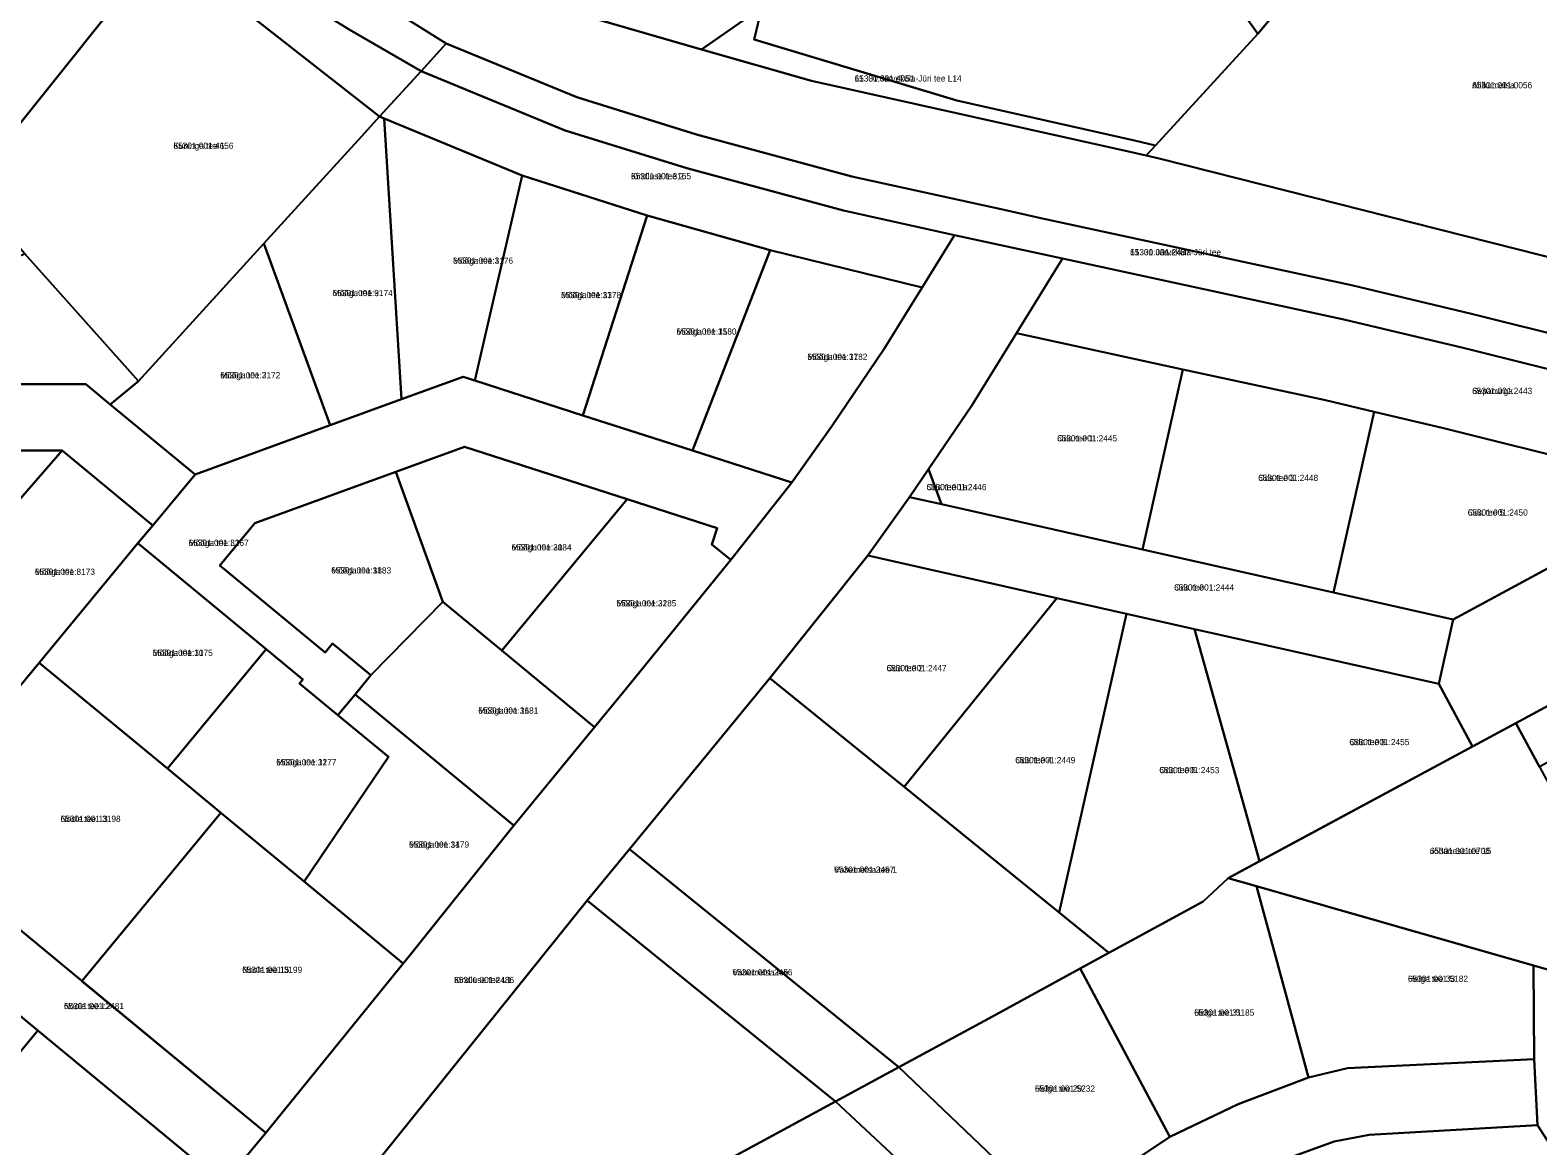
# Model space of a CAD drawing. Extents: x 543236 to 563717, y 6566033 to 6588992.
# Drawn here: x 546570 to 546934.3, y 6582798.1 to 6583067.8 of the extents above; entities that cross this region are included whole.
import ezdxf

# ---------------------------------------------------------------- set-up
doc = ezdxf.new("R2010")
doc.units = 0
for name, color, linetype in [('L_AADRESS', 7, 'Continuous'), ('PIIR', 7, 'Continuous'), ('TUNNUS', 7, 'Continuous')]:
    doc.layers.add(name, color=color, linetype=linetype)

msp = doc.modelspace()

# ---------------------------------------------------------------- linework, layer by layer
at = {"layer": 'PIIR'}
for points in [[(546824.7, 6583127.22), (546857.69, 6583150.07), (546891.19, 6583101.69), (546893.24, 6583098.72), (546866.63, 6583066.87), (546863.9, 6583070.8)], [(546744.91, 6583065.56), (546746.77, 6583073.24), (546824.7, 6583127.22), (546863.9, 6583070.8), (546866.63, 6583066.87), (546841.91, 6583039.95), (546836.85, 6583041.1), (546793.9, 6583050.82)], [(546601.81, 6583088.17), (546579.76, 6583110.6), (546587.72, 6583117.51), (546608.42, 6583096.43), (546617.02, 6583089.31), (546631.52, 6583077.62), (546647.09, 6583067.98), (546664.44, 6583057.9), (546654.4, 6583046.93)], [(546592.18, 6583076.12), (546569.09, 6583101.29), (546579.76, 6583110.6), (546601.81, 6583088.17), (546654.4, 6583046.93), (546650.13, 6583042.2), (546634.72, 6583025.32), (546626.48, 6583016.25), (546596.15, 6582982.97), (546568.74, 6583013.76), (546554.83, 6583029.43)], [(546613.46, 6583102.71), (546629.64, 6583090.21), (546650.79, 6583076.96), (546670.53, 6583064.59), (546664.44, 6583057.9), (546647.09, 6583067.98), (546631.52, 6583077.62), (546617.02, 6583089.31), (546608.42, 6583096.43)], [(546534.12, 6583087.49), (546566.53, 6583099.04), (546569.09, 6583101.29), (546592.18, 6583076.12), (546554.83, 6583029.43), (546551.45, 6583038.88)], [(546839.65, 6583037.5), (546841.91, 6583039.95), (546866.63, 6583066.87), (546893.24, 6583098.72), (546896.91, 6583097.6), (546991.71, 6583068.46), (546953.5, 6583008.77), (546843.14, 6583036.66)], [(546758.82, 6583055.55), (546732.2, 6583063.15), (546746.77, 6583073.24), (546744.91, 6583065.56), (546793.9, 6583050.82), (546836.85, 6583041.1), (546841.91, 6583039.95), (546839.65, 6583037.5), (546835.39, 6583038.45)], [(546456.84, 6583059.94), (546471.94, 6583065.32), (546476.92, 6583067.09), (546478.83, 6583061.73), (546473.85, 6583059.96), (546478.92, 6583045.71), (546502.02, 6583033.43), (546505.87, 6583022.63), (546515.78, 6582994.85), (546520.29, 6582982.2), (546583.47, 6582982.2), (546589.34, 6582977.35), (546609.88, 6582960.38), (546599.62, 6582948.1), (546577.72, 6582966.2), (546509.01, 6582966.2), (546489.73, 6583020.25), (546489.03, 6583022.22), (546465.95, 6583034.48)], [(546670.53, 6583064.59), (546702.13, 6583051.56), (546731.04, 6583042.61), (546768.56, 6583032.44), (546805.33, 6583024.33), (546814.25, 6583022.37), (546889.3, 6583006.12), (546918.28, 6582999.27), (546993.56, 6582980.46), (547036.14, 6582972.21), (547055.46, 6582968.62), (547045.02, 6582962.99), (547043.55, 6582962.16), (546991.71, 6582972.17), (546916.25, 6582991.02), (546887.44, 6582997.84), (546819.45, 6583012.57), (546793.36, 6583018.28), (546766.52, 6583024.18), (546728.68, 6583034.46), (546699.25, 6583043.54), (546664.44, 6583057.9)], [(546664.44, 6583057.9), (546699.25, 6583043.54), (546728.68, 6583034.46), (546766.52, 6583024.18), (546793.36, 6583018.28), (546785.54, 6583005.61), (546748.79, 6583014.62), (546719.11, 6583022.96), (546688.86, 6583032.68), (546655.52, 6583046.44), (546654.4, 6583046.93)], [(546654.4, 6583046.93), (546655.52, 6583046.44), (546659.72, 6582978.58), (546642.53, 6582972.3), (546626.49, 6583016.26), (546634.72, 6583025.32), (546650.13, 6583042.2)], [(546655.52, 6583046.44), (546688.86, 6583032.68), (546677.47, 6582983.09), (546674.61, 6582984.01), (546659.72, 6582978.58)], [(546688.86, 6583032.68), (546719.11, 6583022.96), (546703.57, 6582974.69), (546677.47, 6582983.09)], [(546719.11, 6583022.96), (546748.79, 6583014.62), (546730.06, 6582966.17), (546703.57, 6582974.69)], [(546626.49, 6583016.26), (546642.53, 6582972.3), (546609.88, 6582960.38), (546589.34, 6582977.35), (546596.16, 6582982.98)], [(546748.79, 6583014.62), (546785.54, 6583005.61), (546782.23, 6583000.25), (546776.38, 6582990.78), (546763.71, 6582972.09), (546754.02, 6582958.46), (546730.06, 6582966.17)], [(546515.78, 6582994.85), (546568.74, 6583013.76), (546596.15, 6582982.97), (546589.34, 6582977.35), (546583.47, 6582982.2), (546520.29, 6582982.2)], [(546819.45, 6583012.57), (546887.44, 6582997.84), (546916.25, 6582991.02), (546991.71, 6582972.17), (547043.55, 6582962.16), (547015.74, 6582947.15), (546987.39, 6582952.63), (546948.33, 6582962.39), (546911.52, 6582971.59), (546894.72, 6582975.56), (546883.02, 6582978.33), (546848.55, 6582985.79), (546808.3, 6582994.52)], [(546808.3, 6582994.52), (546848.55, 6582985.79), (546838.75, 6582942.28), (546790.19, 6582953.21), (546787.09, 6582961.67), (546797.54, 6582977.08)], [(546848.55, 6582985.79), (546883.02, 6582978.33), (546894.72, 6582975.56), (546884.9, 6582931.9), (546838.75, 6582942.28)], [(546609.88, 6582960.38), (546642.53, 6582972.3), (546659.72, 6582978.58), (546674.61, 6582984.01), (546677.47, 6582983.09), (546703.57, 6582974.69), (546730.06, 6582966.17), (546754.02, 6582958.46), (546739.34, 6582939.78), (546734.7, 6582943.49), (546735.98, 6582947.46), (546714.24, 6582954.45), (546674.94, 6582967.1), (546658.39, 6582961.06), (546624.28, 6582948.6), (546615.87, 6582938.43), (546641.31, 6582917.41), (546643.07, 6582919.54), (546652.32, 6582911.9), (546648.5, 6582907.27), (546644.36, 6582902.26), (546635.11, 6582909.9), (546635.9, 6582910.86), (546627.02, 6582918.19), (546596.05, 6582943.78), (546599.62, 6582948.1)], [(546894.72, 6582975.56), (546911.52, 6582971.59), (546948.33, 6582962.39), (546943.61, 6582941.43), (546913.87, 6582925.38), (546884.9, 6582931.9)], [(546509.01, 6582966.2), (546577.72, 6582966.2), (546542.69, 6582925.9), (546538.28, 6582929.54), (546515.31, 6582948.52)], [(546577.72, 6582966.2), (546599.62, 6582948.1), (546596.05, 6582943.78), (546572.2, 6582914.91), (546565.62, 6582906.95), (546542.69, 6582925.9)], [(546658.39, 6582961.06), (546674.94, 6582967.1), (546714.24, 6582954.45), (546683.98, 6582917.84), (546669.7, 6582929.64)], [(546624.28, 6582948.6), (546658.39, 6582961.06), (546669.7, 6582929.64), (546652.32, 6582911.9), (546643.07, 6582919.54), (546641.31, 6582917.41), (546615.87, 6582938.43)], [(546787.09, 6582961.67), (546790.19, 6582953.21), (546782.44, 6582954.95)], [(546948.33, 6582962.39), (546987.39, 6582952.63), (547015.74, 6582947.15), (546928.97, 6582900.33), (546918.5, 6582894.68), (546910.35, 6582909.77), (546913.87, 6582925.38), (546943.61, 6582941.43)], [(547043.55, 6582962.16), (547045.02, 6582962.99), (547053.27, 6582961.5), (547068.09, 6582961.29), (547058.83, 6582956.3), (547047.81, 6582950.34), (547035.02, 6582943.44), (546994.72, 6582921.68), (547023.22, 6582868.88), (547012.66, 6582863.18), (547003.63, 6582879.9), (547007.15, 6582881.8), (546987.94, 6582917.39), (546981.16, 6582919.42), (546943.32, 6582898.99), (546945.22, 6582895.47), (546934.67, 6582889.77), (546928.97, 6582900.33), (547015.74, 6582947.15)], [(546714.24, 6582954.45), (546735.98, 6582947.46), (546734.7, 6582943.49), (546739.34, 6582939.78), (546713.46, 6582907.92), (546706.4, 6582899.32), (546683.98, 6582917.84)], [(546782.44, 6582954.95), (546790.19, 6582953.21), (546838.75, 6582942.28), (546884.9, 6582931.9), (546913.87, 6582925.38), (546910.35, 6582909.77), (546851.31, 6582923.05), (546834.91, 6582926.75), (546818.1, 6582930.53), (546772.39, 6582940.81)], [(546596.05, 6582943.78), (546627.02, 6582918.19), (546603.15, 6582889.34), (546572.2, 6582914.91)], [(546772.39, 6582940.81), (546818.1, 6582930.53), (546781.16, 6582884.91), (546748.72, 6582911.17)], [(546669.7, 6582929.64), (546683.98, 6582917.84), (546706.4, 6582899.32), (546686.88, 6582875.56), (546648.5, 6582907.27), (546652.32, 6582911.9)], [(546818.1, 6582930.53), (546834.91, 6582926.75), (546818.62, 6582854.57), (546781.16, 6582884.91)], [(546834.91, 6582926.75), (546851.31, 6582923.05), (546867.06, 6582866.92), (546859.5, 6582862.82), (546853.4, 6582857.23), (546830.61, 6582844.81), (546818.62, 6582854.57)], [(546851.31, 6582923.05), (546910.35, 6582909.77), (546918.5, 6582894.68), (546867.06, 6582866.92)], [(546627.02, 6582918.19), (546635.9, 6582910.86), (546635.11, 6582909.9), (546644.36, 6582902.26), (546656.57, 6582892.17), (546636.23, 6582862.02), (546616.11, 6582878.64), (546603.15, 6582889.34)], [(546572.2, 6582914.91), (546603.15, 6582889.34), (546616.11, 6582878.64), (546582.51, 6582837.98), (546582.05, 6582838.36), (546539.65, 6582873.39), (546538.61, 6582874.25), (546565.62, 6582906.95)], [(546748.72, 6582911.17), (546781.16, 6582884.91), (546818.62, 6582854.57), (546830.61, 6582844.81), (546823.73, 6582840.99), (546802.52, 6582829.41), (546779.87, 6582817.15), (546714.78, 6582869.82)], [(546648.5, 6582907.27), (546686.88, 6582875.56), (546686.47, 6582875.06), (546661.61, 6582844.02), (546660.17, 6582842.24), (546636.23, 6582862.02), (546656.57, 6582892.17), (546644.36, 6582902.26)], [(546928.97, 6582900.33), (546934.67, 6582889.77), (546954.35, 6582853.3), (546949.62, 6582837.04), (546933.24, 6582841.73), (546866.3, 6582860.88), (546859.5, 6582862.82)], [(546616.11, 6582878.64), (546636.23, 6582862.02), (546660.17, 6582842.24), (546626.94, 6582801.27), (546582.51, 6582837.98)], [(546529.46, 6582861.05), (546539.65, 6582873.39), (546582.05, 6582838.36), (546626.94, 6582801.27), (546616.68, 6582788.99), (546571.86, 6582826.02)], [(546714.78, 6582869.82), (546779.87, 6582817.15), (546764.57, 6582808.86), (546704.61, 6582857.46)], [(546845.35, 6582800.32), (546823.73, 6582840.99), (546830.61, 6582844.81), (546853.4, 6582857.23), (546859.5, 6582862.82), (546866.3, 6582860.88), (546878.85, 6582814.7), (546861.89, 6582808.2)], [(546493.83, 6582817.93), (546529.46, 6582861.05), (546571.86, 6582826.02), (546536.23, 6582782.9), (546510.39, 6582804.25)], [(546878.85, 6582814.7), (546866.3, 6582860.88), (546933.24, 6582841.73), (546933.45, 6582819.12), (546888.35, 6582816.91)], [(546704.61, 6582857.46), (546764.57, 6582808.86), (546722.52, 6582786.05), (546678.14, 6582762.03), (546665.85, 6582755.32), (546633.59, 6582737.86), (546585.24, 6582711.61), (546584.34, 6582711.11), (546651.49, 6582791.37)], [(546817.24, 6582781.51), (546779.87, 6582817.15), (546802.52, 6582829.41), (546823.73, 6582840.99), (546845.35, 6582800.32)], [(546933.45, 6582819.12), (546933.24, 6582841.73), (546949.62, 6582837.04), (546968.88, 6582831.7), (546990.21, 6582825.54), (546994.88, 6582809.22), (546948.14, 6582784.9), (546946.5, 6582784.11), (546934.26, 6582803.13)], [(546536.23, 6582782.9), (546571.86, 6582826.02), (546616.68, 6582788.99), (546580.62, 6582746.23), (546539.15, 6582780.49)], [(546793.59, 6582781.78), (546764.57, 6582808.86), (546779.87, 6582817.15), (546817.24, 6582781.51), (546798.93, 6582771.65)], [(546756.97, 6582749.43), (546722.52, 6582786.05), (546764.57, 6582808.86), (546793.59, 6582781.78), (546798.93, 6582771.65)], [(546891.86, 6582757.53), (546873.6, 6582795.04), (546885.11, 6582799.19), (546893.51, 6582800.81), (546934.26, 6582803.13), (546946.5, 6582784.11), (546900.82, 6582761.74)]]:
    msp.add_lwpolyline(points, close=True, dxfattribs=at)
for points in [[(547294.1, 6582901.21), (547206.95, 6582950.98), (547196.64, 6582953.98), (547152.11, 6582958.67), (547122.02, 6582961.9), (547060.4, 6582971.13), (547055.46, 6582968.62), (547036.14, 6582972.21), (546993.56, 6582980.46), (546918.28, 6582999.27), (546889.3, 6583006.12), (546814.25, 6583022.37), (546805.33, 6583024.33), (546768.56, 6583032.44), (546731.04, 6583042.61), (546702.13, 6583051.56), (546670.53, 6583064.59), (546650.79, 6583076.96)], [(546746.77, 6583073.24), (546732.2, 6583063.15), (546707.4, 6583070.31)], [(546707.4, 6583070.31), (546732.2, 6583063.15), (546758.82, 6583055.55), (546835.39, 6583038.45), (546839.65, 6583037.5), (546843.14, 6583036.66), (546953.5, 6583008.77), (547033.94, 6582990.72), (547039.08, 6582989.6), (547095.89, 6582981.55), (547195.38, 6582971.01), (547213.24, 6582965.81), (547223.73, 6582959.82)], [(546616.68, 6582788.99), (546626.94, 6582801.27), (546660.17, 6582842.24), (546661.61, 6582844.02), (546686.47, 6582875.06), (546706.4, 6582899.32), (546713.46, 6582907.92), (546739.34, 6582939.78), (546754.02, 6582958.46), (546763.71, 6582972.09), (546776.38, 6582990.78), (546782.23, 6583000.25), (546785.54, 6583005.61), (546793.36, 6583018.28), (546819.45, 6583012.57), (546808.3, 6582994.52), (546797.54, 6582977.08), (546787.09, 6582961.67), (546782.44, 6582954.95), (546772.39, 6582940.81), (546748.72, 6582911.17), (546714.78, 6582869.82), (546704.61, 6582857.46), (546651.49, 6582791.37)], [(546817.24, 6582781.51), (546845.35, 6582800.32), (546861.89, 6582808.2), (546878.85, 6582814.7), (546888.35, 6582816.91), (546933.45, 6582819.12), (546934.26, 6582803.13), (546893.51, 6582800.81), (546885.11, 6582799.19), (546873.6, 6582795.04)]]:
    msp.add_lwpolyline(points, dxfattribs=at)

# ---------------------------------------------------------------- texts
at = {"layer": 'L_AADRESS'}
for s, p in [('11330 Järveküla-Jüri tee L14', (546769.2, 6583055.37)), ('Allikumetsa', (546918.43, 6583053.74)), ('Kuninga tee 1', (546604.61, 6583039.11)), ('Kindluse tee 2', (546715.19, 6583031.75)), ('11330 Järveküla-Jüri tee', (546835.78, 6583013.38)), ('Mõõga tee 11', (546672.19, 6583011.34)), ('Mõõga tee 9', (546643.11, 6583003.51)), ('Mõõga tee 13', (546698.29, 6583003.02)), ('Mõõga tee 15', (546726.18, 6582994.2)), ('Mõõga tee 17', (546757.8, 6582988.09)), ('Mõõga tee 7', (546615.94, 6582983.63)), ('Sepanurga', (546918.44, 6582979.86)), ('Oda tee 1', (546818.14, 6582968.4)), ('Oda tee 3', (546866.72, 6582958.84)), ('Oda tee 1a', (546786.57, 6582956.61)), ('Oda tee 5', (546917.36, 6582950.47)), ('Mõõga tee L2', (546608.3, 6582943.14)), ('Mõõga tee 20', (546686.32, 6582942.05)), ('Mõõga tee 18', (546642.73, 6582936.48)), ('Mõõga tee 8', (546571.15, 6582936.15)), ('Oda tee', (546846.41, 6582932.36)), ('Mõõga tee 22', (546711.66, 6582928.53)), ('Mõõga tee 10', (546599.62, 6582916.56)), ('Oda tee 2', (546776.93, 6582912.86)), ('Mõõga tee 16', (546678.29, 6582902.6)), ('Oda tee 8', (546888.76, 6582894.99)), ('Mõõga tee 12', (546629.48, 6582890.11)), ('Oda tee 4', (546808.03, 6582890.62)), ('Oda tee 6', (546842.84, 6582888.22)), ('Noole tee 13', (546577.36, 6582876.45)), ('Mõõga tee 14', (546661.55, 6582870.22)), ('Johanese tee 15', (546908.21, 6582868.68)), ('Vahemetsa tee 1', (546764.28, 6582864.16)), ('Noole tee 15', (546621.23, 6582839.96)), ('Vahemetsa tee', (546739.71, 6582839.34)), ('Kindluse tee L1', (546672.44, 6582837.49)), ('Helge tee 33', (546902.93, 6582837.79)), ('Noole tee L2', (546578.17, 6582831.19)), ('Helge tee 31', (546851.29, 6582829.62)), ('Helge tee 29', (546812.8, 6582811.25))]:
    msp.add_text(s, height=1.5, dxfattribs=at).set_placement(p)
at = {"layer": 'TUNNUS'}
for s, p in [('65301:001:4051', (546769.2, 6583055.37)), ('65301:001:0056', (546918.43, 6583053.74)), ('65301:001:4656', (546604.61, 6583039.11)), ('65301:001:3165', (546715.19, 6583031.75)), ('65301:001:2487', (546835.78, 6583013.38)), ('65301:001:3176', (546672.19, 6583011.34)), ('65301:001:3174', (546643.11, 6583003.51)), ('65301:001:3178', (546698.29, 6583003.02)), ('65301:001:3180', (546726.18, 6582994.2)), ('65301:001:3182', (546757.8, 6582988.09)), ('65301:001:3172', (546615.94, 6582983.63)), ('65301:001:2443', (546918.44, 6582979.86)), ('65301:001:2445', (546818.14, 6582968.4)), ('65301:001:2448', (546866.72, 6582958.84)), ('65301:001:2446', (546786.57, 6582956.61)), ('65301:001:2450', (546917.36, 6582950.47)), ('65301:001:3167', (546608.3, 6582943.14)), ('65301:001:3184', (546686.32, 6582942.05)), ('65301:001:3183', (546642.73, 6582936.48)), ('65301:001:3173', (546571.15, 6582936.15)), ('65301:001:2444', (546846.41, 6582932.36)), ('65301:001:3185', (546711.66, 6582928.53)), ('65301:001:3175', (546599.62, 6582916.56)), ('65301:001:2447', (546776.93, 6582912.86)), ('65301:001:3181', (546678.29, 6582902.6)), ('65301:001:2455', (546888.76, 6582894.99)), ('65301:001:3177', (546629.48, 6582890.11)), ('65301:001:2449', (546808.03, 6582890.62)), ('65301:001:2453', (546842.84, 6582888.22)), ('65301:001:3198', (546577.36, 6582876.45)), ('65301:001:3179', (546661.55, 6582870.22)), ('65301:001:0708', (546908.21, 6582868.68)), ('65301:001:2457', (546764.28, 6582864.16)), ('65301:001:3199', (546621.23, 6582839.96)), ('65301:001:2456', (546739.71, 6582839.34)), ('65301:001:2486', (546672.44, 6582837.49)), ('65301:001:5182', (546902.93, 6582837.79)), ('65301:001:2481', (546578.17, 6582831.19)), ('65301:001:5185', (546851.29, 6582829.62)), ('65301:001:5232', (546812.8, 6582811.25))]:
    msp.add_text(s, height=1.5, dxfattribs=at).set_placement(p)

doc.saveas('drawing.dxf')
